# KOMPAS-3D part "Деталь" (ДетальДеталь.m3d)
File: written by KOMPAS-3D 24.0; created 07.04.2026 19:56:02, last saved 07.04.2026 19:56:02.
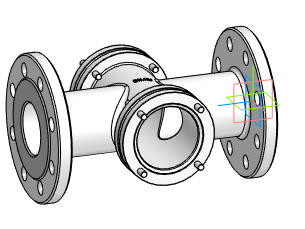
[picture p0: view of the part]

Document properties: Автор: Main; Полное имя файла: D:\DN.ru Аутсерс\Стекло смотровое DN.ru\Исходники\Стекло смотровое DN.ru SG2-34G-F тип В ГОСТ 21836-2021 Ду65 Ру16, углеродистая сталь, фланцевое\ДетальДеталь.m3d

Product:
- Body: Твердое тело1  | qty 1
- Part/product: Деталь
    additional columns: Типовые

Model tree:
1. Твердое тело1  (labels: Твердое тело1)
